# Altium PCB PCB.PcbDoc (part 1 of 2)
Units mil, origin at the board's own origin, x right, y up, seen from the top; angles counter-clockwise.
Board outline 1141.73 x 1220.47 mil, 2 copper layers (Top Layer, Bottom Layer), stack 61.8 mil thick; 114 components, 66 nets, 300 pads, 104 vias.
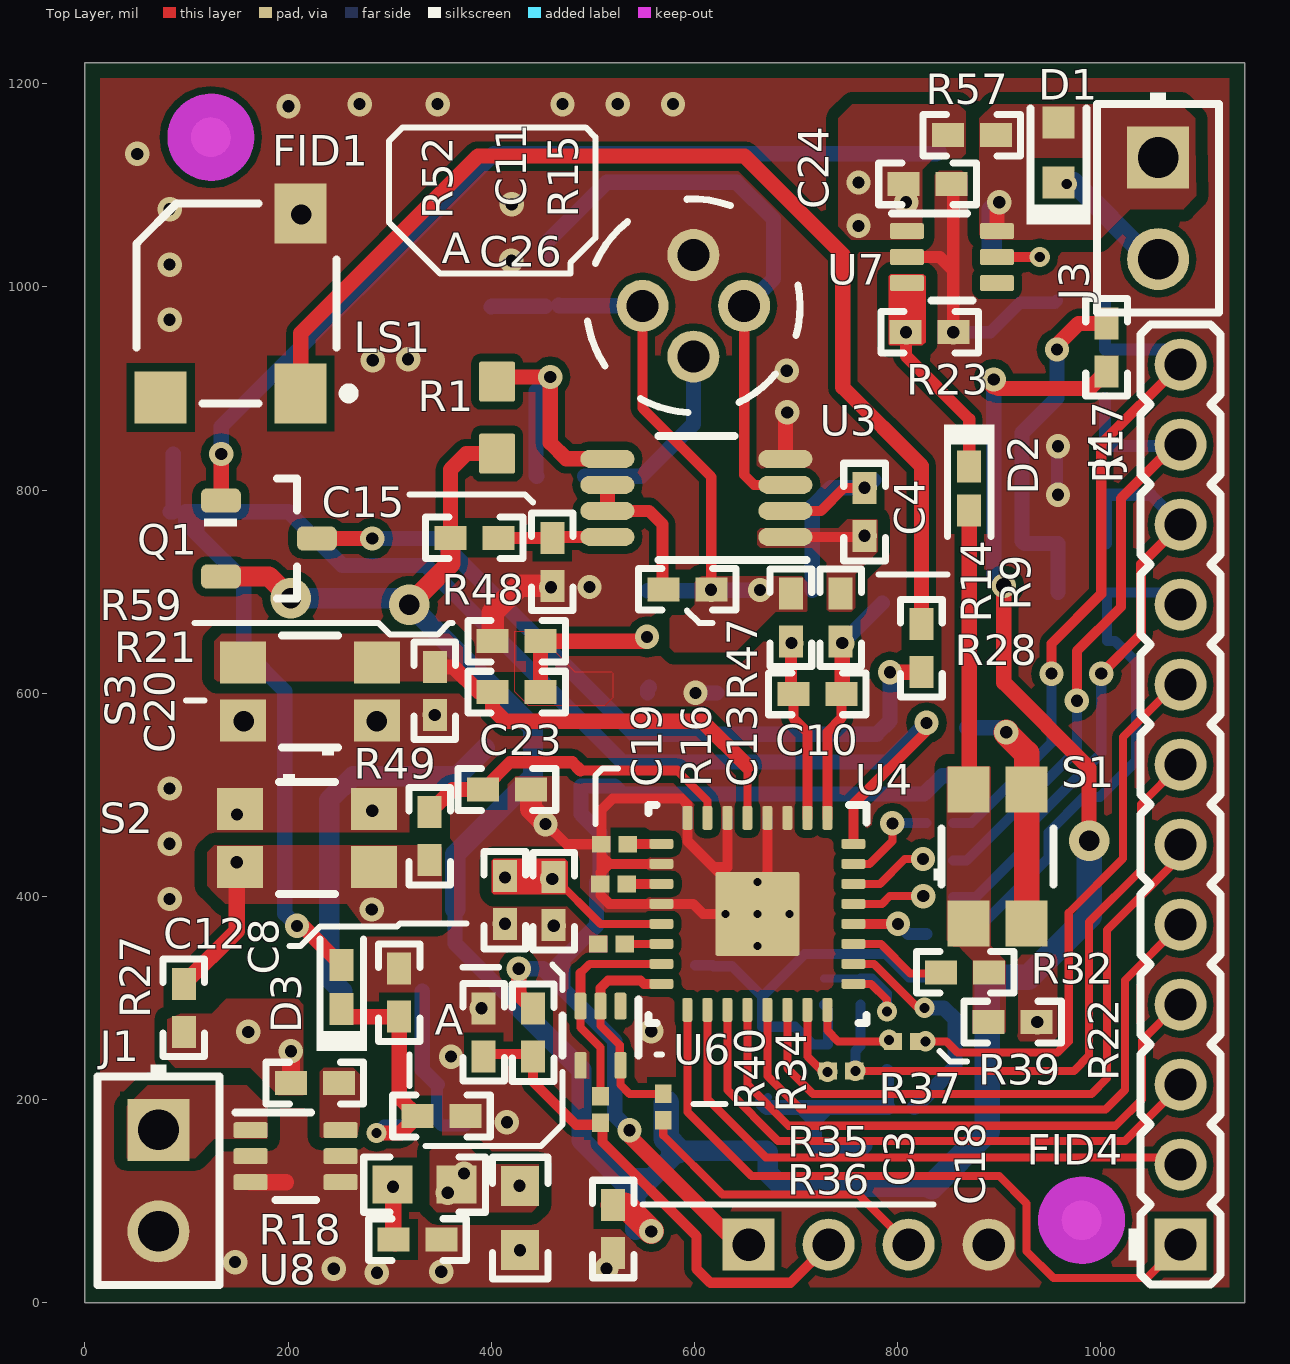
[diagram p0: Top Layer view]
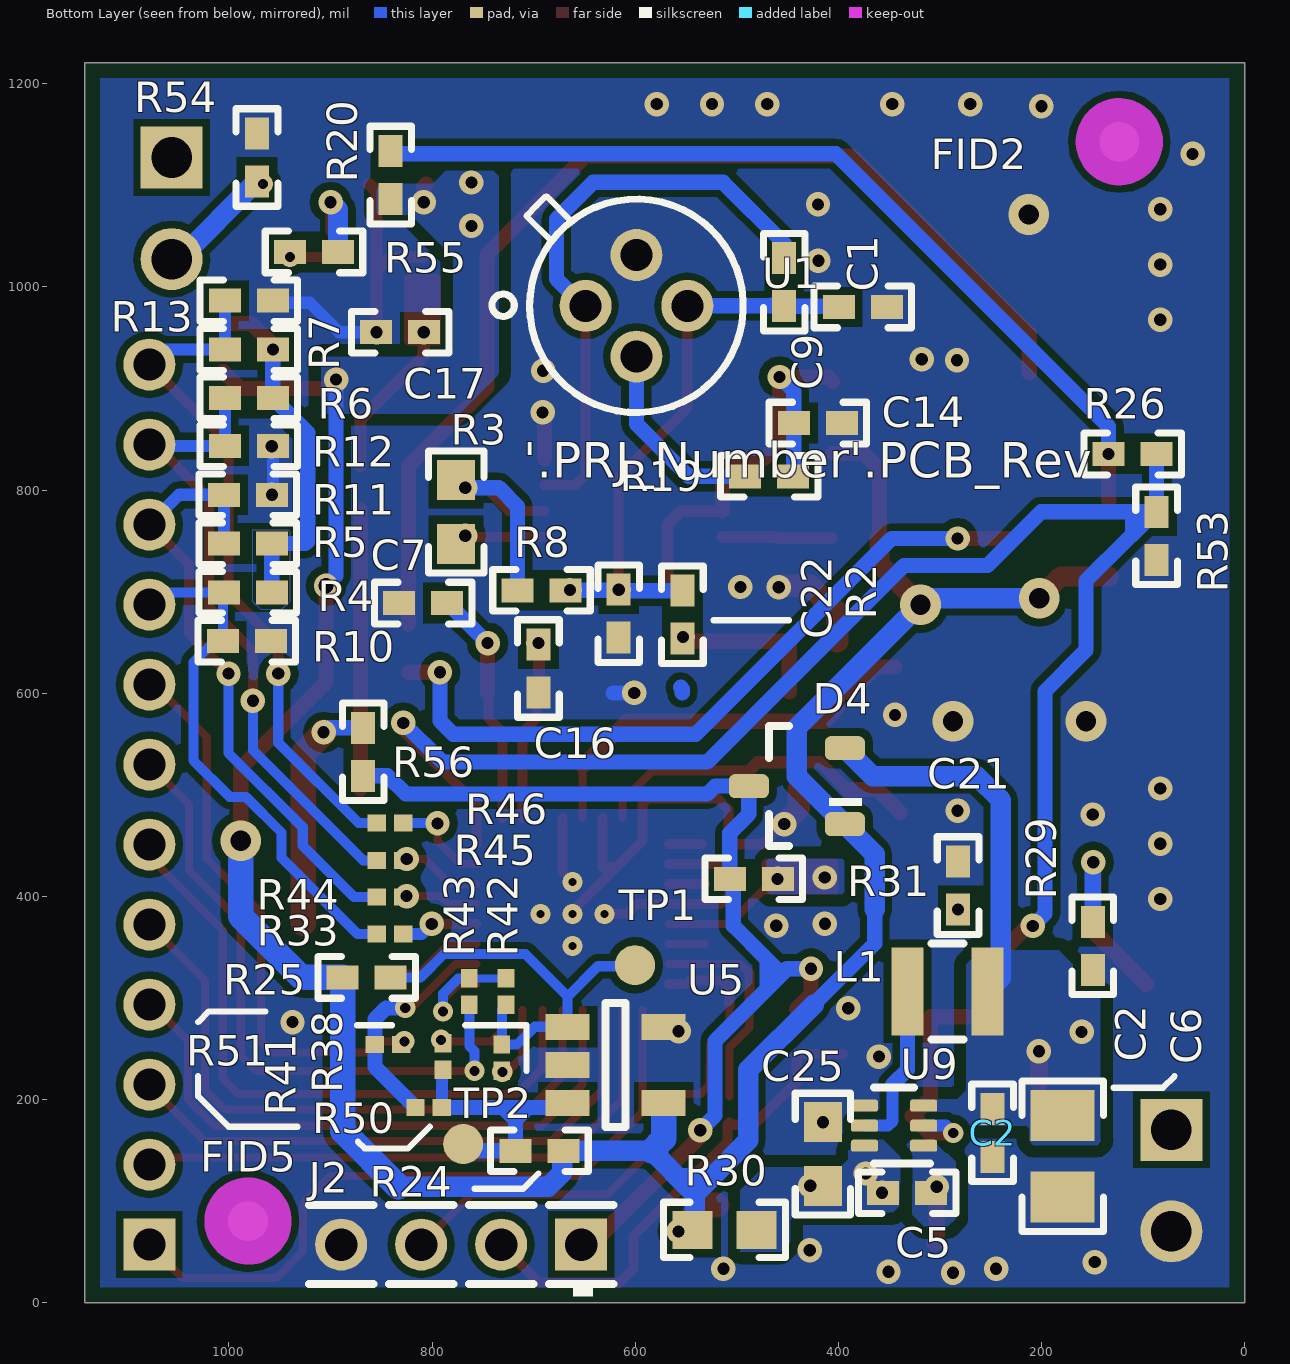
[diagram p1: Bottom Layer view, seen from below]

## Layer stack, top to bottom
Top Solder: solder mask 0.4, Solder Resist, Dk 3.5
Top Layer: signal copper 1.4
Dielectric 2: core 59, FR-4 High TG, Dk 4.2
Bottom Layer: signal copper 1.4
Bottom Solder: solder mask 0.4, Solder Resist, Dk 3.5

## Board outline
0,0 1141.73,0 1141.73,1220.47 0,1220.47

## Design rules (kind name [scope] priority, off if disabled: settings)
AcuteAngle [All] p1: minimum=4.50000000000000E+0001 checktracksonly=FALSE
AssemblyTestPointUsage [All] p1: valid=2
BoardOutlineClearance BoardOutlineClearance_poly [OnCopper and IsPoly] p1: gap=15 ignorepadtopadclearanceinfootprint=FALSE
Clearance [All] p1: gap=7 ignorepadtopadclearanceinfootprint=FALSE except(0: Arc-SMDPad Track-SMDPad; 8: SMDPad-Fill SMDPad-Poly SMDPad-Region Via-Fill Via-Poly Via-Region; 12: Fill-Fill Fill-Poly Fill-Region Poly-Poly Poly-Region Region-Region)
Clearance Clearance_Poly [InPolygon] p2: gap=15 ignorepadtopadclearanceinfootprint=FALSE
ComponentClearance ComponentClearance_TieNet [HasFootprint('Net-Tie_10mil')] p1: gap=0 collisioncheckmode=3 verticalgap=0 showdistances=FALSE
ComponentClearance "ComponentClearance_Spark Gap" [HasFootprint('GAP')] p2: gap=0 collisioncheckmode=3 verticalgap=0 showdistances=FALSE
ComponentClearance ComponentClearance_Logo [InComponentClass(Logo)] p3: gap=0 collisioncheckmode=3 verticalgap=100000 showdistances=FALSE
ComponentClearance ComponentClearance_ScrewToNut [(HasFootprint('NY PMS 440 0025 PH')) vs (HasFootprint('Keystone_1902C'))] p4: gap=10 collisioncheckmode=3 verticalgap=10 showdistances=FALSE
ComponentClearance ComponentClearance_MountingHoles [InComponentClass('Mounting Holes')] p5: gap=25 collisioncheckmode=3 verticalgap=100000 showdistances=FALSE
ComponentClearance ComponentClearance_THtoTH [IsThruComponent vs IsThruComponent] p6: gap=10 collisioncheckmode=3 verticalgap=10 showdistances=FALSE
ComponentClearance [All] p7 off: gap=10 collisioncheckmode=3 verticalgap=10 showdistances=FALSE
DiffPairsRouting [All] p1: maxlimit=100 minlimit=10 mostfreqgap=10 toplayer_minwidth=15 toplayer_maxwidth=15 toplayer_prefwidth=15 bottomlayer_minwidth=15 bottomlayer_maxwidth=15 bottomlayer_prefwidth=15 maxuncoupledlength=1000
FabricationTestPointUsage TestPointUsage [All] p1: valid=2 allowmultiple=FALSE
FabricationTestpoint Testpoint [All] p1: side=3 testpointundercomponent=TRUE minsize=40 maxsize=100 preferedsize=60 minholesize=0 maxholesize=40 preferedholesize=32 testpointgrid=1 allowsidetop=TRUE allowsidebottom=TRUE usegrid=TRUE gridtolerance=0.01
FanoutControl Fanout_LCC [IsLCC] p1: bgadir=Out bgaviamode=Centered fanoutstyle=Auto fanoutdirection=Alternating viagrid=1 // Fanout_LCC (Default Rule)
FanoutControl Fanout_BGA [IsBGA] p2: bgadir=Out bgaviamode=Centered fanoutstyle=Auto fanoutdirection=Alternating viagrid=1 // Fanout_BGA (Default Rule)
FanoutControl Fanout_Default [All] p4: bgadir=Out bgaviamode=Centered fanoutstyle=Auto fanoutdirection=Alternating viagrid=1 // Fanout_Default (Default Rule)
FanoutControl Fanout_Small [(CompPinCount < 5)] p5: bgadir=Out bgaviamode=Centered fanoutstyle=Auto fanoutdirection=OutThenIn viagrid=1 // Fanout_Small (Default Rule)
HoleSize [All] p1: absolutevalues=TRUE maxlimit=251 minlimit=6 maxpercent=80.000 minpercent=20.000
MinimumAnnularRing [All] p1 off: minimumring=5
MinimumSolderMaskSliver "MinimumSolderMaskSliver_Spark Gap" [All vs HasFootprint('SPARK_GAP2')] p1: minsoldermaskwidth=0
MinimumSolderMaskSliver MinimumSolderMaskSliver_Logo [InComponentClass('Logo') vs InComponentClass('Logo')] p2: minsoldermaskwidth=0.7
MinimumSolderMaskSliver [All] p3: minsoldermaskwidth=2
NetAntennae [All] p1 off: netantennaetolerance=10
PlaneConnect [All] p1: planeconnectstyle=Relief reliefexpansion=10 reliefentries=4 reliefconductorwidth=10 reliefairgap=10
PolygonConnect [All] p1: connectstyle=Direct reliefconductorwidth=10 reliefentries=4 polygonreliefangle="90 Angle" airgapwidth=10
RoutingCorners [All] p1: cornerstyle=45-Degree minsetback=5 maxsetback=5
RoutingVias "RoutingVias_Room_.65mm Pitch" [WithinRoom('Room_.65mm Pitch')] p1: holewidth=10 width=20 viastyle="Through Hole" minholewidth=6 minwidth=18 maxholewidth=10 maxwidth=22
RoutingVias [All] p2: holewidth=12 width=24 viastyle="Through Hole" minholewidth=10 minwidth=20 maxholewidth=20 maxwidth=40
SMDNeckDown [All] p1 off: percent=40.000
SMDToCorner [All] p1: distance=0
ShortCircuit [InNet('GND') vs InNet('SIGNAL GND')] p1: allowed=TRUE
SilkToBoardRegionClearance [Not ((IsComment or IsDesignator) And (Hide <> 'False')) and not InRegion(1000,500,4000,800)] p1:
SilkToSilkClearance [All] p1: silktosilkclearance=0
SilkToSolderMaskClearance SilkscreenOverComponentPads_SparkGap [HasFootprint('SPARK_GAP2')] p1 off: minsilkscreentomaskgap=-10 clearancetoexposedcopper=TRUE
SilkToSolderMaskClearance SilkscreenOverComponentPads_1 [All vs All - HasFootprint('SPARK_GAP2')] p2 off: minsilkscreentomaskgap=2 clearancetoexposedcopper=TRUE
SolderMaskExpansion [All] p1: expansion=2
ViasUnderSMD [WithinRoom('Room_.4mm Pitch')] p1: allowed=TRUE
Width [All] p1: maxlimit=100 minlimit=8 preferedwidth=15 checkconnectedcopper=TRUE
12 further rules are at their usual default settings.

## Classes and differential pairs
component class FiducialMark: FID1 FID2 FID4 FID5
component class Header: J1 J2 J3 J4
component class "Host Controller Section_1": C1 C2 C3 C4 C5 C6 C7 C8 C9 C10 C11 C12 C13 C14 C15 C16 C17 C18 C19 C20 C21 C22 C23 C24 C25 C26 D1 D2 D3 D4 J1 J2 J3 J4 L1 LS1 Q1 R1 R2 R3 R4 R5 R6 R7 R8 R9 R10 R11 R12 R13 R14 R15 R16 R17 R18 R19 R20 R21 R22 R23 R24 R25 R26 R27 R28 R29 R30 R31 R32 R33 R34 R35 R36 R37 R38 R39 R40 R41 R42 R43 R44 R45 R46 R47 R48 R49 R50 R51 R52 R53 R54 R55 R56 R57 R59 S1 S2 S3 TP1 TP2 U1 U3 U4 U5 U6 U7 U8 U9
component class Logo: Logo2
component class Hardware: FID1 FID2 FID4 FID5 Logo2 Logo3

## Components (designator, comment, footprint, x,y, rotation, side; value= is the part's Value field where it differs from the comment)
C1 "C1005JB1V105K050BC" 0402 453.43,1004.62 r270 bottom value=1uF
C2 "GRM155R71E104KE14D" 0402 248.37,167.39 r270 bottom value=0.1uF
C3 "GRM188R61A226ME15D" 0603 428.37,83.39 r270 top value=22uF
C4 "C1005JB1V105K050BC" 0402 767.37,778.39 r270 top value=1uF
C5 "GRM1555C1H1R1BA01D" 0402 332.37,108.39 r0 bottom value=1.1pF
C6 "C2012X5R1A336M125AC" 0805_HV 179.37,144.39 r270 bottom value=33uF
C7 "C1005JB1V105K050BC" 0402 808.75,688.77 r0 bottom value=1uF
C8 "GRM155R60J106ME47D" 0402 461.37,395.39 r270 top value=10uF
C9 "C1005JB1V105K050BC" 0402 376.15,980.31 r180 bottom value=1uF
C10 "C1005JB1V105K050BC" 0402 720.87,599.39 r180 top value=1uF
C11 "C0402C112J5GAC7867" 0402 392.47,266.39 r90 top value=1100pF
C12 "GRM155R71E104KE14D" 0402 413.37,396.39 r270 top value=0.1uF
C13 "GRM033R60J474KE90D" 0201_033 518.37,353.39 r180 top value=0.47uF
C14 "C1005JB1V105K050BC" 0402 420.42,866 r180 bottom value=1uF
C15 "C1005JB1V105K050BC" 0402 460.06,729.39 r270 top value=1uF
C16 "C1005JB1V105K050BC" 0402 695.37,624.39 r270 bottom value=1uF
C17 "C1005JB1V105K050BC" 0402 831.37,955.39 r0 bottom value=1uF
C18 "C1005JB1V105K050BC" 0402 519.97,72.77 r270 top value=1uF
C19 "GRM033R61E104KE14J" 0201_033 521.37,451.39 r180 top value=0.1uF
C20 "GRM155R71E104KE14D" 0402 344.37,602.39 r270 top value=0.1uF
C21 "GRM155R71E104KE14D" 0402 282.37,410.8 r90 bottom value=0.1uF
C22 "GRM155R71E104KE14D" 0402 616.37,678.39 r270 bottom value=0.1uF
C23 "GRM155R71E104KE14D" 0402 415.37,505.34 r0 top value=0.1uF
C24 "C1005JB1V105K050BC" 0402 829.37,1101.39 r180 top value=1uF
C25 "GRM188R61A226ME15D" 0603 415.37,146.39 r90 bottom value=22uF
C26 "GRM155R71E104KE14D" 0402 350.99,183.96 r0 top value=0.1uF
D1 "LTST-C190GKT" LED_LTST-C190 958.37,1132.39 r270 top value=Green
D2 "1N4148X-TP" SOD-523 870.37,801.74 r270 top value=75V
D3 "1N4148X-TP" SOD-523 252.75,310.71 r90 top value=75V
D4 "BAT54C-7-F" SOT-23 441.05,508.67 r0 bottom value=30V
FID1 "Fiducial" Fiducial10-20 123.85,1147.32 r0 top
FID2 "Fiducial" Fiducial10-20 123.65,1142.86 r180 bottom
FID4 "Fiducial" Fiducial10-20 980.98,81.35 r0 top
FID5 "Fiducial" Fiducial10-20 981.24,80.53 r180 bottom
J1 "PEC01DAAN" Sullins_PxC01DAAN 72.37,120.39 r270 top
J2 "PTT-104-01-L-S" Samtec_PTT-104-01-x-S 771.37,57.39 r0 bottom
J3 "PEC01DAAN" Sullins_PxC01DAAN 1056.37,1077.39 r270 top
J4 "M22-2511205" Harwin_M22-2511205 1078.37,490.46 r90 top
L1 "LQM2HPN2R2MG0L" 1008 292.75,306.74 r180 bottom value=2.2uH
Logo2 "Texas Instruments" TI_Stacked_Overlay_Small 1290.23,404.73 r90 top
Logo3 "FCC disclaimer" FCC_disclaimer 3078.31,4369.38 r0 top
LS1 "SMT-0540-T-2-R" PUI_SMT-0540-S-R 149.37,983.8 r180 top
Q1 "BC857C-7-F" SOT-23 181.07,752.39 r0 top value="45 V"
R1 "CPF0603B1M0E1" CPF_0603 405.7,871.37 r270 top value=1.00Meg
R2 "CRCW04020000Z0ED" 0402 553.62,677.39 r270 bottom value=0
R3 "RG1608P-204-B-T5" 0603 776.37,778.39 r270 bottom value=200k
R4 "RC0402FR-0747KL" 0402 981.37,699.39 r180 bottom value=47.0k
R5 "RC0402FR-0747KL" 0402 981.37,747.39 r180 bottom value=47.0k
R6 "RC0402FR-0747KL" 0402 980.37,890.74 r180 bottom value=47.0k
R7 "RC0402FR-0747KL" 0402 980.37,938.39 r180 bottom value=47.0k
R8 "ERA-2AEB102X" 0402 692.37,701.39 r0 bottom value=1.00k
R9 "CRCW04021K00JNED" 0402 743.87,674.39 r270 top value=1.0k
R10 "RC0402FR-0747KL" 0402 982.37,651.39 r0 bottom value=47.0k
R11 "RC0402FR-0747KL" 0402 981.37,795.39 r0 bottom value=47.0k
R12 "RC0402FR-0747KL" 0402 980.37,843.57 r0 bottom value=47.0k
R13 "RC0402FR-0747KL" 0402 980.37,986.39 r0 bottom value=47.0k
R14 "CRCW04021K00JNED" 0402 694.87,674.39 r270 top value=1.0k
R15 "RC0402FR-0747KL" 0402 441.05,265.99 r90 top value=47.0k
R16 "ERJ-1GE0R00C" 0201 520.37,412.39 r0 top value=0
R17 "CRCW04020000Z0ED" 0402 1005.54,940.46 r270 top value=0
R18 "CRCW04020000Z0ED" 0402 226.37,216.39 r180 top value=0
R19 "RT0402BRD07102KL" 0402 468.24,813.64 r180 bottom value=102k
R20 "CRCW0402100KJNED" 0402 840.75,1110.11 r270 bottom value=100k
R21 "CRCW04021K00JNED" 0402 424.87,601.27 r180 top value=1.0k
R22 "ERJ-2RKF4701X" 0402 913.1,276.39 r180 top value=4.70k
R23 "CRCW040210M0JNED" 0402 831.37,955.39 r180 top value=10Meg
R24 "CRCW04022K20JNED" 0402 694.37,149.71 r180 bottom value=2.2k
R25 "CRCW04022K20JNED" 0402 864.37,320.39 r0 bottom value=2.2k
R26 "CRCW0402100KJNED" 0402 110.54,835.53 r0 bottom value=100k
R27 "RC0402FR-0747KL" 0402 97.37,290.39 r270 top value=47.0k
R28 "CRCW0402680RJNED" 0402 823.37,644.39 r270 top value=680
R29 "CRCW040217K4FKED" 0402 149.75,351.41 r90 bottom value=17.4k
R30 "ERJ-3GEY0R00V" 0603 512.1,71.83 r180 bottom value=0
R31 "ERJ-2RKF33R0X" 0402 483.37,417.39 r180 bottom value=33.0
R32 "CRCW04020000Z0ED" 0402 866.37,325.39 r180 top value=0
R33 "ERJ-1GE0R00C" 0201 841.37,363.02 r0 bottom value=0
R34 "ERJ-1GE0R00C" 0201 569.25,192.73 r90 top value=0
R35 "RT0603BRD07453KL" 0603 334.37,116.39 r0 top value=453k
R36 "RG1005P-104-B-T5" 0402 327.37,62.39 r180 top value=100k
R37 "ERJ-1GE0R00C" 0201 744.36,228.39 r0 top value=0
R38 "ERJ-1GE0R00C" 0201 731.37,241.39 r90 bottom value=0
R39 "ERJ-1GE0R00C" 0201 808.32,257.39 r0 top value=0
R40 "ERJ-1GE0R00C" 0201 507.37,190.39 r90 top value=0
R41 "ERJ-1GE0R00C" 0201 789.35,242.39 r270 bottom value=0
R42 "ERJ-1GE0R00C" 0201 727.37,306.39 r270 bottom value=0
R43 "ERJ-1GE0R00C" 0201 763.37,306.39 r270 bottom value=0
R44 "ERJ-1GE0R00C" 0201 841.37,399.39 r0 bottom value=0
R45 "ERJ-1GE0R00C" 0201 841.37,435.39 r0 bottom value=0
R46 "ERJ-1GE0R00C" 0201 841.37,472.39 r0 bottom value=0
R47 "ERJ-2GEJ101X" 0402 592.87,702.39 r0 top value=100
R48 "ERJ-2RKF33R0X" 0402 383.37,753.01 r0 top value=33.0
R49 "CRCW04021K00JNED" 0402 339.37,459.39 r90 top value=1.0k
R50 "ERJ-1GE0R00C" 0201 803.36,192.39 r180 bottom value=0
R51 "ERJ-1GE0R00C" 0201 843.33,254.39 r180 bottom value=0
R52 "CRCW0402100KJNED" 0402 309.37,305.34 r270 top value=100k
R53 "CRCW040222K0JNED" 0402 86.91,755.01 r90 bottom value=22k
R54 "CRCW0402680RJNED" 0402 972.37,1127.39 r270 bottom value=680
R55 "CRCW0402100RJNED" 0402 916.25,1034.39 r180 bottom value=100
R56 "CRCW0402100RJNED" 0402 867.79,542.39 r270 bottom value=100
R57 "CRCW04020000Z0ED" 0402 872.99,1149.33 r180 top value=0
R59 "RC0402FR-0747KL" 0402 424.87,651.27 r0 top value=47.0k
S1 "434153017835" SW_434153017835 898.37,439.39 r90 top
S2 "434153017835" SW_434153017835 218.37,457.39 r0 top
S3 "434153017835" SW_434153017835 221.31,601.85 r180 top
TP1 "TP_SM_1MM" TP_SM_1MM 600.37,332.39 r90 bottom
TP2 "TP_SM_1MM" TP_SM_1MM 769.37,156.39 r90 bottom
U1 "TS318-11C55" TE_TS318-11C55 598.87,981.39 r90 bottom locked
U3 "TLV2333IDGKR" DGK0008A_N 601.87,792.39 r180 top
U4 "MSP430I2041TRHBR" RHB0032M 661.84,382.9 r270 top locked
U5 "AT24C02C-STUM-T" SOT-23-5 619.37,234.39 r180 bottom
U6 "TPD2E2U06DRLR" DRL0005A 507.37,263.02 r270 top
U7 "TPS22919DCKR" DCK0006A_N 853.37,1029.39 r0 top
U8 "LM66100DCKR" DCK0006A_N 207.37,144.39 r0 top
U9 "TPS61023DRL" DRL0006A 345.37,174.39 r0 bottom

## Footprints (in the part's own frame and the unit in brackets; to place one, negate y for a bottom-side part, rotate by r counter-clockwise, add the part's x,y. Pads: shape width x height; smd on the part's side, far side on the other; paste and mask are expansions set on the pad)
0201 [mm] "Data from Kemet datasheet CC101_COM dated 7/28/11"
  rect 0.46x0.42 smd mask+0.048: 1(-0.33,0) 2(0.33,0)
  body extent -0.31,-0.16 0.31,0.16, height 0.26
0201_033 [mm] "SMD, 2-Leads, Height 0.33mm"
  rect 0.46x0.42 smd mask+0.048: 1(-0.33,0) 2(0.33,0)
  body extent -0.31,-0.16 0.31,0.16, height 0.33
0402 [mm] "0402 from SM-752 data"
  rect 0.8x0.6 smd: 1(-0.6,0) 2(0.6,0)
  silkscreen extent -1.22,-0.52 1.22,0.52, body extent -0.55,-0.3 0.55,0.3, height 0.6
0603 [mm] "0603 from SM-752 data"
  rect 1x0.95 smd: 1(-0.8,0) 2(0.8,0)
  silkscreen extent -1.52,-0.69 1.52,0.69, body extent -0.87,-0.47 0.87,0.47, height 1
0805_HV [mil] "0805 with 30mil clearance between pads"
  rect 50x63 smd: 1(-40,0) 2(40,0)
  silkscreen extent -74,-40 74,40, body extent -43,-29 43,29, height 57
1008 [mm] "SMD, Body 2.5x2mm, Height 1.2mm"
  rect 0.8x2.2 smd: 1(-1,0) 2(1,0)
  silkscreen extent -0.4,-1.2 0.4,1.2, body extent -1.35,-1.1 1.35,1.1, height 1.2
CPF_0603 [mm] "SMD, 2-Leads, Body 1.55x0.8mm"
  rrect11% 1x0.9 smd: 1(-0.9,0) 2(0.9,0)
  body extent -0.82,-0.45 0.82,0.45, height 0.55
DCK0006A_N [mm] "SOT23, 6-Leads, Body 2x1.3mm, Pitch 0.65mm, Lead Span 2.1mm, IPC Medium Density"
  rrect25% 0.85x0.4 smd: 1(-1.125,0.65) 2(-1.125,0) 3(-1.125,-0.65) 4(1.125,-0.65) 5(1.125,0) 6(1.125,0.65)
  silkscreen extent -1.5,-1.09 0.51,1.09, body extent -1.14,-1 1.14,1, height 0.95
DGK0008A_N [mm] "TSOP, 8-Leads, Body 3x3mm, Pitch 0.65mm, IPC Medium Density"
  oval 1.35x0.45 smd: 1(-2.225,0.975) 2(-2.225,0.325) 3(-2.225,-0.325) 4(-2.225,-0.975) 5(2.225,-0.975) 6(2.225,-0.325) 7(2.225,0.325) 8(2.225,0.975)
  silkscreen extent -2.75,-1.55 0.95,1.55, body extent -2.45,-1.5 2.45,1.5, height 0.96
DRL0005A [mm] "SOTFL, 5-Flat Leads, Body 1.2x1.6x0.6mm, Pitch 0.5mm, TI recommended"
  rrect33% 0.67x0.3 smd: 1(-0.74,0.5) 2(-0.74,0) 3(-0.74,-0.5) 4(0.74,-0.5) 5(0.74,0.5)
  silkscreen extent -0.9,-0.95 0.5,0.95, body extent -0.85,-0.85 0.85,0.85, height 0.62
DRL0006A [mm] "SOTFL, 6-Flat Leads, Body 1.2x1.6x0.6mm, Pitch 0.5mm, TI recommended"
  rrect33% 0.67x0.3 smd: 1(-0.74,0.5) 2(-0.74,0) 3(-0.74,-0.5) 4(0.74,-0.5) 5(0.74,0) 6(0.74,0.5)
  silkscreen extent -0.9,-0.95 0.5,0.95, body extent -0.8,-0.8 0.8,0.8, height 0.61
FCC_disclaimer [mil]
Fiducial10-20 [mm]
  round 1 smd mask+0.5: 1(0,0)
  Top Layer keep-out circle w1.178: c0,0 r0.5
Harwin_M22-2511205 [mm] "Header, 2mm, 12x1, TH"
  rect 1.3x1.3 hole 0.8: 1(-11,0)
  round 1.3 hole 0.8: 2(-9,0) 3(-7,0) 4(-5,0) 5(-3,0) 6(-1,0) 7(1,0) 8(3,0) 9(5,0) 10(7,0) 11(9,0) 12(11,0)
  silkscreen extent -12,-1 12,1.3, body extent -12,-1 12,1, height 5
LED_LTST-C190 [mm] "Lite-On"
  rect 0.8x0.8 smd: 1(-0.75,0) 2(0.75,0)
  silkscreen extent -1.1,-0.8 1.8,0.8, body extent -0.85,-0.45 0.85,0.45, height 0.9
PUI_SMT-0540-S-R [mm] "SMD, 3-Leads, Body 5x5mm"
  rect 1.3x1.5 smd: 1(-1.6,2.25) 2(-1.6,-2.25)
  rect 1.3x1.3 smd: 3(1.9,2.35)
  silkscreen extent -2.93,-2.5 2.5,2.5, body extent -2.5,-2.7 2.5,2.7, height 2
RHB0032M [mm] "QFN, 32-Leads, Body 5x5mm, Pitch 0.5mm, Thermal Pad 2.1x2.1mm"
  rrect40% 0.6x0.25 smd: 1(-2.4,1.75) 2(-2.4,1.25) 3(-2.4,0.75) 4(-2.4,0.25) 5(-2.4,-0.25) 6(-2.4,-0.75) 7(-2.4,-1.25) 8(-2.4,-1.75) 17(2.4,-1.75) 18(2.4,-1.25) 19(2.4,-0.75) 20(2.4,-0.25) 21(2.4,0.25) 22(2.4,0.75) 23(2.4,1.25) 24(2.4,1.75)
  rrect40% 0.25x0.6 smd: 9(-1.75,-2.4) 10(-1.25,-2.4) 11(-0.75,-2.4) 12(-0.25,-2.4) 13(0.25,-2.4) 14(0.75,-2.4) 15(1.25,-2.4) 16(1.75,-2.4) 25(1.75,2.4) 26(1.25,2.4) 27(0.75,2.4) 28(0.25,2.4) 29(-0.25,2.4) 30(-0.75,2.4) 31(-1.25,2.4) 32(-1.75,2.4)
  rrect11% 0.94x0.94 on Top Paste: 33(-0.57,0.57) 33(-0.57,-0.57) 33(0.57,-0.57) 33(0.57,0.57)
  rrect5% 2.1x2.1 smd paste-1.725: 33(0,0)
  silkscreen extent -2.73,-2.73 2.73,2.72, body extent -2.55,-2.55 2.55,2.55, height 1.01
Samtec_PTT-104-01-x-S [mm] "Header, 2mm, 4x1, TH"
  rect 1.3x1.3 hole 0.81: 1(-3,0)
  round 1.3 hole 0.81: 2(-1,0) 3(1,0) 4(3,0)
  silkscreen extent -3.81,-0.99 3.81,1.3, body extent -4,-0.99 4,0.99, height 4.7
SOD-523 [mm] "NXP Semiconductor recommended land pattern, nominal STEP model"
  rect 0.8x0.6 smd paste-0.05: 1(-0.55,0) 2(0.55,0)
  silkscreen extent -1.6,-0.64 1.2,0.63, body extent -0.8,-0.4 0.8,0.4, height 0.72
SOT-23 [mm] "SOT23, 3-Leads, Body 2.9x1.3mm, Pitch 0.95mm, Lead Span 2.5mm, IPC Medium Density"
  rrect50% 1x0.6 smd: 1(-1.2,0.95) 2(-1.2,-0.95) 3(1.2,0)
  silkscreen extent -1.62,-1.5 0.7,1.5, body extent -1.16,-1.45 1.21,1.45, height 1
SOT-23-5 [mm] "SOT23, 5-Leads, Body 2.9x1.6mm, Pitch 0.95mm, Lead Span 2.8mm, IPC Medium Density"
  rect 1.1x0.65 smd: 1(-1.2,0.95) 2(-1.2,0) 3(-1.2,-0.95) 4(1.2,-0.95) 5(1.2,0.95)
  silkscreen extent -0.25,-1.55 0.25,1.55, body extent -1.42,-1.46 1.42,1.46, height 1.08
Sullins_PxC01DAAN [mm] "Header, 2.54mm, 1x2, TH"
  rect 1.55x1.55 hole 1.016: 1(-1.27,0)
  round 1.55 hole 1.016: 2(1.27,0)
  silkscreen extent -2.9,-1.53 2.61,1.53, body extent -2.61,-1.53 2.61,1.53, height 8.71
SW_434153017835 [mm] "SMD, 4-Leads, Body 3.5x2.9mm"
  rect 1.15x1.05 smd: 1(-1.675,0.725) 2(-1.675,-0.725) 3(1.675,0.725) 4(1.675,-0.725)
  silkscreen extent -0.7,-1.4 0.7,1.6, body extent -2.15,-1.45 2.15,1.45, height 1.7
TE_TS318-11C55 [mm] "THERMOPHILE SENSOR, TO-18, TH-4P"
  round 1.3 hole 0.8: 1(0,1.27) 2(-1.27,0) 3(0,-1.27) 4(1.27,0)
  silkscreen extent -2.67,-2.67 2.73,3.61, body extent -2.67,-2.67 2.67,2.67, height 2.85
TI_Stacked_Overlay_Small [mil]
  silkscreen extent -418,-98 418,98
TP_SM_1MM [mm] "1mm Test Point, SMT"
  round 1 smd paste-0.5: 1(0,0)

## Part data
C1 C4 C7 C9 C10 C14 C15 C16 C17 C18 C24: library part CMP-0006253-2, "CAP, CERM, 1 uF, 35 V, +/- 10%, JB, 0402", Cap_Case=0402, Manufacturer=TDK, Supplier Part Number 1=445-11014-1-ND, TempCo=JB, Tolerance_%=10%, Value1=Unknown, Value2=35V, ValueDisplayed=1uF
C2 C12 C20 C21 C22 C23 C26: "CAP, CERM, 0.1 µF, 25 V,+/- 10%, X7R, 0402", Cap_Case=0402, Manufacturer=MuRata, Supplier Part Number 1=490-10698-1-ND, TempCo=X7R, Tolerance_%=10, Value2=25V, ValueDisplayed=0.1µF
C3 C25: "CAP, CERM, 22 µF, 10 V,+/- 20%, X5R, 0603", Cap_Case=0603, Manufacturer=MuRata, Supplier Part Number 1=490-10476-1-ND, TempCo=X5R, Tolerance_%=20, Value2=10V, ValueDisplayed=22µF
C5: "CAP, CERM, 1.1 pF, 50 V,+/- 10%, C0G/NP0, 0402", Cap_Case=0402, Manufacturer=MuRata, Supplier Part Number 1=490-8189-1-ND, TempCo=C0G/NP0, Tolerance_%=10, Value2=50V, ValueDisplayed=1.1pF
C6: "CAP, CERM, 33 µF, 10 V,+/- 20%, X5R, 0805", Cap_Case=0805, Manufacturer=TDK, Supplier Part Number 1=445-8238-1-ND, TempCo=X5R, Tolerance_%=20, Value1="0.001694 ohm", Value2=10V, ValueDisplayed=33µF
C8: library part CMP-0078624-1, "CAP, CERM, 10 µF, 6.3 V,+/- 20%, X5R, 0402", Cap_Case=0402, Manufacturer=MuRata, Supplier Part Number 1=490-13239-1-ND, TempCo=X5R, Tolerance_%=20%, Value2=6.3V, ValueDisplayed=10µF
C11: library part CMP-0006238-2, "CAP, CERM, 1100 pF, 50 V, +/- 5%, C0G/NP0, 0402", Cap_Case=0402, Manufacturer=Kemet, Supplier Part Number 1=399-9948-1-ND, TempCo=C0G/NP0, Tolerance_%=5%, Value1=Unknown, Value2=50V, ValueDisplayed=1100pF
C13: "CAP, CERM, 0.47 µF, 6.3 V,+/- 10%, X5R, 0201", Cap_Case=0201, Manufacturer=MuRata, Supplier Part Number 1=490-10409-1-ND, TempCo=X5R, Tolerance_%=10, Value2=6.3V, ValueDisplayed=0.47µF
C19: "CAP, CERM, 0.1 µF, 25 V,+/- 10%, X5R, 0201", Cap_Case=0201, Manufacturer=MuRata, Supplier Part Number 1=GRM033R61E104KE14D-ND, TempCo=X5R, Tolerance_%=10, Value2=25V, ValueDisplayed=0.1µF
D1: library part CMP-0002827-2, "LED, Green, SMD", Color=green, Manufacturer=Lite-On, Power_TotalModule=100mW, Supplier Part Number 1=160-1183-1-ND, Value1=0.1W, Value2=2.1V
D2 D3: library part CMP-0076957-1, "Diode, Switching, 75 V, 0.3 A, SOD-523", Manufacturer="Micro Commercial Components", Supplier Part Number 1=1N4148XTPMSCT-ND, Value1=0.3A, Value2=1.25V
D4: library part CMP-0028453-2, "Diode, Schottky, 30 V, 0.2 A, SOT-23", Manufacturer="Diodes Inc.", Value1=0.2A, Value2=0.65V
FID1 FID2 FID4 FID5: library part CMP-0077181-1, "Fiducial mark.  There is nothing to buy or mount.", Manufacturer=N/A
J1 J3: library part CMP-0054594-1, "Header, 2.54mm, 1x2, Tin, Black, TH", Color=Black, Current_A=3A, Manufacturer="Sullins Connector Solutions", Supplier Part Number 1=S2012E-01-ND, Voltage_V=1.8kV
J2: library part CMP-0055572-1, "Header, 2mm, 4x1, Gold, TH", Color=Black, Current_A=2.9A, Manufacturer=Samtec
J4: library part CMP-0075238-1, "Header, 2mm, 12x1, Gold, TH", Color=Black, Current_A=1A, Manufacturer=Harwin, Supplier Part Number 1=M22-2511205-ND, Voltage_V=500V
L1: library part CMP-0058752-1, "Inductor, Multilayer, Ferrite, 2.2 uH, 1.3 A, 0.08 ohm, SMD", Manufacturer=MuRata, Supplier Part Number 1=490-5114-1-ND, Value1="0.08 ohm", Value2=1.3A, ValueDisplayed=2.2uH
Logo2: library part CMP-0074838-1, "Texas Instrument Corporate Signature"
Logo3: library part CMP-0074847-1, "FCC_disclaimer"
LS1: library part CMP-0001959-1, "Buzzer, 2 to 4V, 4kHz, SMD", Manufacturer="PUI Audio", Supplier Part Number 1=668-1060-1-ND
Q1: library part CMP-0000316-2, "Transistor, PNP, 45 V, 0.1 A, SOT-23", Manufacturer="Diodes Inc.", Supplier Part Number 1=BC857C-FDICT-ND, Value1="0.1 A", Value2=600
R1: library part CMP-0079989-2, "RES, 1.00 M, 0.1%, 0.063 W, 0603", Manufacturer="TE Connectivity", Power_W=63mW, Supplier Part Number 1=A102234CT-ND, TempCo="25 ppm/C", Tolerance_%=0.1%, Value2=0.063W, Value_Code=1M00, ValueDisplayed=1.00M
R2 R17 R18 R32 R57: library part CMP-0026822-1, "RES, 0, 5%, 0.063 W, 0402", Manufacturer=Vishay-Dale, Power_W=63mW, Supplier Part Number 1=541-0.0JCT-ND, TempCo="200 ppm/C", Tolerance_%=5%, Value2=0.063W, Value_Code=0000, ValueDisplayed=0
R3: "RES, 200 k, 0.1%, 0.1 W, 0603", Manufacturer="Susumu Co Ltd", Power_W=0.1, Supplier Part Number 1=RG16P200KBCT-ND, TempCo="25 ppm/C", Tolerance_%=0.1%, Value2=0.1W, Value_Code=200k
R4 R5 R6 R7 R10 R11 R12 R13 R15 R27 R59: "RES, 47.0 k, 1%, 0.0625 W, 0402", Manufacturer="Yageo America", Power_W=0.0625, Supplier Part Number 1=311-47.0KLRCT-ND, TempCo="100 ppm/C", Tolerance_%=1, Value1=1%, Value2=0.0625W, Value_Code=47k0, ValueDisplayed=47.0k
R8: "RES, 1.00 k, 0.1%, 0.063 W, 0402", Manufacturer=Panasonic, Power_W=0.063, Supplier Part Number 1=P1.0KDCCT-ND, TempCo="25 ppm/C", Tolerance_%=0.1%, Value2=0.063W, Value_Code=1k00, ValueDisplayed=1.00k
R9 R14 R21 R49: library part CMP-0026852-3, "RES, 1.0 k, 5%, 0.063 W, AEC-Q200 Grade 0, 0402", Manufacturer=Vishay-Dale, Power_W=63mW, Supplier Part Number 1=541-1.0KJCT-ND, TempCo="200 ppm/C", Tolerance_%=5%, Value2=0.063W, Value_Code=1k00, ValueDisplayed=1.0k
R16 R33 R34 R37 R38 R39 R40 R41 R42 R43 R44 R45 R46 R50 R51: "RES, 0, 5%, 0.05 W, 0201", Manufacturer=Panasonic, Power_W=0.05, Supplier Part Number 1=P0.0AGCT-ND, TempCo="600 ppm/C", Tolerance_%=5, Value1=5%, Value2=0.05W, Value_Code=0000, ValueDisplayed=0
R19: library part RG1005P-104-B-T5, "RES, 100 k, 0.1%, 0.063 W, 0402", Manufacturer=Yageo, Power_W=0.063, TempCo="25 ppm/C", Tolerance_%=0.1%, Value2=0.063W, Value_Code=102k
R20 R26 R52: "RES, 100 k, 5%, 0.063 W, 0402", Manufacturer=Vishay-Dale, Power_W=0.063, Supplier Part Number 1=541-100KJCT-ND, TempCo="200 ppm/C", Tolerance_%=5, Value1=5%, Value2=0.063W, Value_Code=100k
R22: "RES, 4.70 k, 1%, 0.1 W, 0402", Manufacturer=Panasonic, Power_W=0.1, Supplier Part Number 1=P4.70KLCT-ND, TempCo="100 ppm/C", Tolerance_%=1, Value1=1%, Value2=0.1W, Value_Code=4k70, ValueDisplayed=4.70k
R23: "RES, 10 M, 5%, 0.063 W, 0402", Manufacturer=Vishay-Dale, Power_W=0.063, Supplier Part Number 1=541-10MJCT-ND, TempCo="200 ppm/C", Tolerance_%=5, Value1=5%, Value2=0.063W, Value_Code=10M0, ValueDisplayed=10M
R24 R25: library part CMP-0026890-3, "RES, 2.2 k, 5%, 0.063 W, 0402", Manufacturer=Vishay-Dale, Power_W=63mW, Supplier Part Number 1=541-2.2KJCT-ND, TempCo="200 ppm/C", Tolerance_%=5%, Value2=0.063W, Value_Code=2k20, ValueDisplayed=2.2k
R28 R54: "RES, 680, 5%, 0.063 W, 0402", Manufacturer=Vishay-Dale, Power_W=0.063, Supplier Part Number 1=541-680JCT-ND, TempCo="200 ppm/C", Tolerance_%=5, Value1=5%, Value2=0.063W, Value_Code=680R, ValueDisplayed=680
R29: "RES, 17.4 k, 1%, 0.063 W, 0402", Manufacturer=Vishay-Dale, Power_W=0.063, Supplier Part Number 1=541-17.4KLCT-ND, TempCo="100 ppm/C", Tolerance_%=1, Value1=1%, Value2=0.063W, Value_Code=17k4, ValueDisplayed=17.4k
R30: "RES, 0, 5%, 0.1 W, 0603", Manufacturer=Panasonic, Power_W=0.1, Supplier Part Number 1=P0.0GCT-ND, TempCo="600 ppm/C", Tolerance_%=5, Value1=5%, Value2=0.1W, Value_Code=0000, ValueDisplayed=0
R31 R48: "RES, 33.0, 1%, 0.1 W, 0402", Manufacturer=Panasonic, Power_W=0.1, Supplier Part Number 1=P33.0LCT-ND, TempCo="100 ppm/C", Tolerance_%=1, Value1=1%, Value2=0.1W, Value_Code=33R0, ValueDisplayed=33.0
R35: "RES, 453 k, 0.1%, 0.1 W, 0603", Manufacturer="Yageo America", Power_W=0.1, TempCo="25 ppm/C", Value1=0.1%, Value2=0.1W, Value_Code=453k
R36: "RES, 100 k, 0.1%, 0.063 W, 0402", Manufacturer="Susumu Co Ltd", Power_W=0.063, Supplier Part Number 1=RG10P100KBCT-ND, TempCo="25 ppm/C", Tolerance_%=0.1%, Value2=0.063W, Value_Code=100k
R47: "RES, 100, 5%, 0.1 W, AEC-Q200 Grade 0, 0402", Manufacturer=Panasonic, Power_W=0.1, Supplier Part Number 1=P100JCT-ND, TempCo="200 ppm/C", Tolerance_%=5, Value1=5%, Value2=0.1W, Value_Code=100R, ValueDisplayed=100
R53: "RES, 22 k, 5%, 0.063 W, 0402", Manufacturer=Vishay-Dale, Power_W=0.063, Supplier Part Number 1=541-22KJCT-ND, TempCo="200 ppm/C", Tolerance_%=5, Value1=5%, Value2=0.063W, Value_Code=22k0, ValueDisplayed=22k
R55 R56: "RES, 100, 5%, 0.063 W, 0402", Manufacturer=Vishay-Dale, Power_W=0.063, Supplier Part Number 1=541-100JCT-ND, TempCo="200 ppm/C", Tolerance_%=5, Value1=5%, Value2=0.063W, Value_Code=100R, ValueDisplayed=100
S1 S2 S3: library part CMP-0002302-1, "Switch, SPST, Off-Mom, 0.05 A, 12 VDC, SMD", CurrentRating_mA=50A, Manufacturer="Wurth Elektronik", Supplier Part Number 1=732-10143-1-ND
TP1 TP2: library part CMP-0003825-1, "1mm Test Point, SMT", Manufacturer=Any
U1: "THERMOPILE IR SENSOR, HIGH SIGNAL, TO-18, TH", Manufacturer="TE CONNECTIVITY"
U3: library part CMP-0073533-3, "350 kHz, Low-Noise, RRIO, CMOS Operational Amplifier for Cost-Sensitive Systems, DGK0008A (VSSOP-8)", Alternate Manufacturer="Texas Instruments", Alternate PartNumber=TLV2333IDGKT
U4: library part CMP-0066526-2, "16-bit Mixed Signal Microcontroller, RHB0032M (VQFN-32)", Alternate Manufacturer="Texas Instruments", Alternate PartNumber=MSP430I2041TRHBT
U5: library part CMP-0084264-1, "I2C-Compatible (2-wire) Serial EEPROM, SOT-23-5", Manufacturer=Microchip
U6: library part CMP-0066602-2, "Dual-Channel High-Speed ESD Protection, DRL0005A (SOT-OTHER-5)", Alternate Manufacturer="Texas Instruments"
U7: library part CMP-0081108-1, "5.5-V, 1.5-A, 100-mohm Load Switch with Output Discharge, DCK0006A (SOT-SC70-6)", Alternate Manufacturer="Texas Instruments", Alternate PartNumber=TPS22919DCKT
U8: library part CMP-0085651-1, "+/-6V, Low IQ Ideal Diode with Input Polarity Protection, DCK0006A (SOT-SC70-6)", Alternate Manufacturer="Texas Instruments", Alternate PartNumber=LM66100DCKT
U9: library part CMP-0860667-1, "3-A BOOST CONVERTER WITH 0.5V ULTRA-LOW INPUT VOLTAGE, DRL0006A (SOT-5X3-6)", Alternate Manufacturer="Texas Instruments"

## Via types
v1: diameter 24, hole 12, Top Layer to Bottom Layer, 83 vias
v2: diameter 20, hole 10, Top Layer to Bottom Layer, 9 vias
v3: diameter 40, hole 20, Top Layer to Bottom Layer, 6 vias
v4: diameter 19.68, hole 7.87, Top Layer to Bottom Layer, 5 vias
v5: diameter 24, hole 15, Top Layer to Bottom Layer, 1 vias

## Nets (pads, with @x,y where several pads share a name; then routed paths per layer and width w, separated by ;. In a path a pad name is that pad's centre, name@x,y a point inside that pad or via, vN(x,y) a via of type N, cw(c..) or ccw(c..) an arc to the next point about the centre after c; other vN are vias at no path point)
3V3: C18.1 C24.2 D4.1 Q1.2 R1.2 R17.2 R20.2 R24.2 R25.2 R30.1 R48.1 R57.2 U5.4 U7.1 | length 2727.9
  Top Layer w15: R48.1@359.75,753.01 359.75,820.29 375.39,835.94 R1.2@405.7,835.94 ; C24.2@805.75,1101.39 808.24,1098.91 v1(808.24,1083.36) ; v1@894.49,904.49 v1(894.49,908.89) ; v1@894.87,904.11 898.84,900.14 988.85,900.14 R17.2@1005.54,916.84 ; v5(904.43,705.87) 904.43,610.45 988.37,526.5 v3(988.37,454.82)
  Top Layer w20: Q1.2@133.82,714.99 181.03,714.99 v3(202.45,693.57) ; v3(319.37,687.31) 359.75,727.69 R48.1@359.75,753.01 ; v1@894.49,904.49 v1@894.87,904.11 ; v3@987.41,455.78 v3(988.37,454.82)
  Top Layer w25: C18.1@519.97,96.39 531.37,96.39 v1(557.37,70.39)
  Bottom Layer w10: 570.69,136.3 572.13,137.73 572.13,161.68
  Bottom Layer w15: 364.37,387.18 364.37,353.76 424.52,293.61 ; v1(894.49,908.89) 894.49,715.8 v5(904.43,705.87)
  Bottom Layer w20: v3(202.45,693.57) 313.11,693.57 v3(319.37,687.31) 319.83,687.31 441.05,566.09 441.05,518.52 D4.1@393.8,471.27 364.37,441.84 364.37,387.18 ; 424.52,293.61 488.73,229.41 488.73,160.08 525.91,122.89 ; R30.1@541.6,71.83 541.6,107.2 ; 570.69,136.3 557.29,122.89 ; 572.13,137.73 584.1,149.71 R24.2@670.75,149.71 672.02,148.44 672.02,128.23 685.85,114.39 833.33,114.39 ; 525.91,122.89 541.6,107.2 ; 525.91,122.89 557.29,122.89 ; 541.6,107.2 557.29,122.89
  Bottom Layer w25: U5.4@572.13,196.99 572.13,161.68 584.1,149.71 ; 833.33,114.39 887.99,169.06 R25.2@887.99,320.39 928.37,320.39 988.37,380.39 v3(988.37,454.82)
  other v1: 761.34,1060.1 761.34,1102.74
AVSS: C2.2 C3.2 C6.2 C7.2 C8.2 C9.2 C11.2 C12.2 C13.2 C14.2 C15.2 C16.2 C17.2 C18.2 C19.2 C20.2 C21.2 C22.2 C23.2 C24.1 C25.2 C26.2 J1.2 J2.4 LS1.2 R10.1 R11.1 R12.1 R13.1 R16.1 R22.1 R23.1 R29.1 R36.1 R52.1 R53.1 R54.1 R59.1 S2.1 S2.3 S3.1 S3.3 U1.4 U3.4 U4.3 U4.4 U4.6 U4.8 U4.10 U4.12 U4.33@661.84,382.9 U5.2 U5.5 U6.4 U7.2 U8.2 U8.3 U8.4 U8.5 U9.4 | length 1333.1
  Top Layer w8: C3.2@424.87,54.39 C3.2@427.37,51.9 ; v4(661.84,414.4) 671.69,424.24
  Top Layer w9.8: 508.38,422.89 508.38,424.46 508.38,432.39 508.65,432.12 516.04,432.12 U4.10@567.35,432.12 ; 531.36,392.75 U4.12@567.35,392.75 598.52,392.75 ; 592.94,454.82 U4.8@592.94,477.39 592.94,490.82 ; 632.32,428.85 U4.6@632.32,477.39 ; 671.69,424.24 U4.4@671.69,477.39
  Top Layer w10: v1@453.72,471.66 473.99,451.39 C19.2@508.38,451.39 ; 508.38,422.89 508.38,413.39 R16.1@507.38,412.39 ; 508.38,432.39 508.38,439.78 ; 531.36,392.75 516.04,392.75 507.38,401.41 R16.1@507.38,412.39 ; 592.94,454.82 618.91,428.85 ; 592.94,490.82 587.37,496.39 519.37,496.39 508.38,485.4 C19.2@508.38,451.39 ; 598.52,392.75 608.36,382.9 v4(630.35,382.9) ; 632.32,428.85 618.91,428.85 ; v4(661.84,382.9) 661.84,385.92 618.91,428.85 ; R16.1@507.38,412.39 507.38,423.46 508.38,424.46 516.04,432.12 508.38,439.78 ; 508.38,439.78 C19.2@508.38,451.39
  Top Layer w12: U7.2@809.08,1029.39 841.37,1029.39 854.61,1016.15 ; v1(854.61,955.46) 854.61,1016.15 ; R23.1@854.99,955.39 R23.1@854.99,955.46 ; C24.1@861.99,1101.39 854.61,1094.01 854.61,1016.15
  Top Layer w15: U3.4@689.47,830.78 689.47,873.12 691.21,874.87 v1(691.21,876.53)
  Top Layer w16: U8.3@163.08,118.8 197.98,118.8
  Top Layer w22: R59.1@401.25,651.27 401.25,679.45 427.57,705.77 C15.2@460.06,705.77 ; C23.2@438.99,505.34 438.99,486.39 v1@453.72,471.66
  Bottom Layer w12: v1(854.61,955.46) 891.43,955.46 920.37,984.39 954.75,984.39 R13.1@956.75,986.39 ; R12.1@956.75,846.39 956.75,801.39 R11.1@957.75,800.39
  Bottom Layer w15: v1(600.99,600.39) 621.91,600.39
  other v1: 287.37,29.77 350.76,30.61 244.94,33.61 513.34,33.61 147.8,40.16 428.37,51.9 415.37,177.89 360.26,242.4 557.37,267.39 937.37,276.39 390.47,290.02 461.37,371.31 413.37,373.27 83.34,397.55 83.34,451.93 453.37,471.31 149.75,480.77 282.75,484.36 83.34,506.31 344.37,578.77 458.75,704.39 496.61,704.69 957.75,795.39 957.76,843.09 690.76,917.47 283.36,927.87 318.14,928.89 83.34,967.62 83.34,1021.99 419.76,1025.74 83.34,1076.37 420.14,1081.23 51.49,1130.97 200.35,1177.78 270.37,1179.95 347.09,1179.95 470.11,1179.95 524.49,1179.95 578.87,1179.95
  other v3: 156.37,572.39 287.37,572.39 212.88,1071.22
  other v4: 661.84,351.41 693.34,382.9
BATT_PLUS: C2.1 C6.1 D4.2 L1.2 R18.2 R27.2 U9.3 | length 399.6
  Top Layer w18: R18.2@202.75,216.39 v1(202.75,247.77)
  Bottom Layer w20: L1.2@253.37,306.74 240.37,319.74 240.37,495.02 263.87,518.52 366.24,518.52 D4.2@393.8,546.08
  other v1: 160.75,266.77
BOOST_EN: C26.1 D3.1 R52.2 U9.2 | length 244.3
  Top Layer w15: D3.1@252.75,289.05 260.09,281.72 R52.2@309.37,281.72 309.37,201.96 C26.1@327.37,183.96 310.64,167.22 v2(287.03,167.22)
  Bottom Layer w11.8: v2(287.03,167.22) 294.2,174.39 U9.2@316.24,174.39
BOOST_EN_SIG: D3.2 R26.1 R53.2 U4.32 | length 1591.1
  Top Layer w10: U4.32@756.33,451.8 756.33,490.72 828.38,562.77 v1(828.38,570.86)
  Top Layer w15: v1(208.75,371.06) 214.05,371.06 D3.2@252.75,332.36
  Bottom Layer w15: R53.2@83.75,778.64 R53.2@86.91,778.64 R26.1@86.91,835.53 ; v1(208.75,371.06) 196.75,383.06 196.75,602.06 156.37,642.44 156.37,710.85 114.83,752.39 110.29,756.93 ; v1(828.38,570.86) 789.87,532.36 529.16,532.36 335.65,725.87 253.37,725.87 200.61,778.64 110.29,778.64 ; 110.29,756.93 99.02,768.2 99.02,778.64 110.29,778.64 ; 110.29,756.93 110.29,778.64
COM0: J4.9 R4.1 R10.2 R33.2 | length 526.9
  Bottom Layer w10: R33.2@854.36,363.02 873.32,363.02 948.33,438.02 948.33,463.02 983.39,498.08 999.15,498.08 1034.8,533.73 1034.8,630.59 1013.99,651.39 R10.2@1005.99,651.39 1005.99,698.39 R4.1@1004.99,699.39 1066.29,699.39 J4.9@1078.37,687.31
COM1: J4.10 R5.1 R11.2 R44.2 | length 611
  Top Layer w10: v1(1000.37,619.39) 1039.37,658.39 1039.37,727.05 J4.10@1078.37,766.05
  Bottom Layer w10: R44.2@854.36,399.39 876.67,399.39 927.39,450.11 927.39,468.19 1000.37,541.17 v1(1000.37,619.39) ; v1@995.37,624.39 v1@1000.37,624.39
  Bottom Layer w12: R5.1@1004.99,747.39 R11.2@1004.99,795.39 1049.03,795.39 J4.10@1078.37,766.05
COM2: J4.11 R6.1 R12.2 R45.2 | length 664.5
  Top Layer w10: v1(976.37,592.64) 976.37,641.62 1019.75,685 1019.75,791.87 1058.27,830.39 1078.37,830.39 1063.96,844.79 J4.11@1078.37,844.79
  Bottom Layer w10: R45.2@854.36,435.39 867.79,435.39 976.37,543.98 v1(976.37,592.64)
  Bottom Layer w12: R6.1@1003.99,890.74 1003.99,843.39 1076.97,843.39 J4.11@1078.37,844.79
COM3: J4.12 R7.1 R13.2 R46.2 | length 678
  Top Layer w10: v1@951.37,624.39 951.37,648.88 1000.37,697.88 1000.37,845.53 J4.12@1078.37,923.53
  Bottom Layer w10: R46.2@854.36,472.39 872.35,472.39 951.37,551.42 v1(951.37,619.39)
  Bottom Layer w12: R13.2@1003.99,986.39 R7.1@1003.99,938.39 1063.51,938.39 J4.12@1078.37,923.53
I2C_SCL: R25.1 R38.2 R42.2 TP1.1 U5.1 | length 422.4
  Bottom Layer w10: TP1.1@600.37,332.39 617.86,332.39 618.86,331.39 636.86,331.39 666.61,301.64 ; R42.2@727.37,293.4 731.37,289.4 R38.2@731.37,254.39 716.38,254.39 698.97,271.79 U5.1@666.61,271.79 666.61,301.64 ; R25.1@840.75,320.39 811.32,320.39 788.32,343.39 708.37,343.39 666.61,301.64
I2C_SDA: R24.1 R41.2 R50.2 TP2.1 U5.3 | length 301.4
  Bottom Layer w8: U5.3@666.61,196.99 U5.3@672.02,202.39
  Bottom Layer w12: R41.2@789.35,229.4 790.37,228.39 R50.2@790.37,192.39
  Bottom Layer w15: U5.3@666.61,196.99 671.21,192.39 705.8,192.39 ; TP2.1@767.69,154.71 762.69,149.71 R24.1@717.99,149.71 717.99,180.2 ; R50.2@790.37,192.39 730.19,192.39 ; 705.8,192.39 713.91,192.39 ; 705.8,192.39 717.99,180.2 ; 713.91,192.39 730.19,192.39 ; 713.91,192.39 717.99,188.32 717.99,180.2 ; 717.99,180.2 730.19,192.39
MCU_VCC: D4.3 J2.1 R15.2 R31.1 R56.2 | length 1071
  Top Layer w15: v1(427.04,328.96) 427.04,303.61 R15.2@441.05,289.61 ; v1(536.03,169.86) 536.03,164.32 642.97,57.39 J2.1@653.26,57.39
  Bottom Layer w15: v1(427.04,328.96) 450.36,328.96 ; v1(536.03,169.86) 521.54,184.35 521.54,257.77 470.37,308.94 ; R56.2@867.79,518.77 843.84,518.77 825.9,500.82 529.16,500.82 521.31,508.67 D4.3@488.29,508.67 488.29,481.09 506.99,462.39 R31.1@506.99,417.39 503.61,414.01 503.61,371.31 470.37,338.07 ; 450.36,328.96 451.04,328.96 456.15,323.85 470.37,338.07 ; 450.36,328.96 470.37,308.94 ; 470.37,308.94 470.37,338.07
NetC3_1: C3.1 C5.2 C25.1 R30.2 R35.2 U9.6
  other v1: 357.13,108.39 427.75,115.27 373.13,127.39
NetC4_1: C4.1 R3.1 R8.2 U3.2 | length 240.9
  Top Layer w10: U3.2@689.47,779.6 724.57,779.6 746.99,802.01 C4.1@767.37,802.01
  Bottom Layer w15: R8.2@715.99,701.39 715.99,784.01 734.37,802.39 v1(767.37,802.39) 768.87,802.39 R3.1@776.37,809.89
NetC4_2: C4.2 R3.2 R9.1 U3.1 | length 78.2
  Top Layer w10: U3.1@689.47,754.01 766.61,754.01 C4.2@767.37,754.77
  other v1: 767.37,755.01
NetC5_1: C5.1 R35.1 R36.2 U9.1 | length 56.9
  Top Layer w16: v1(303.37,114.39) 303.37,61.76 302.87,61.27 R36.2@305.37,58.77
NetC8_1: C8.1 C12.1 R31.2 U4.13 | length 179.4
  Top Layer w8: C12.1@407.37,420.02 C12.1@408.37,419.02 ; C8.1@461.43,419.02 507.38,373.06 U4.13@567.35,373.06
  Top Layer w12: C12.1@408.37,419.02 C8.1@461.37,419.02 C8.1@461.43,419.02
  other v1: 459.99,417.31 413.49,418.68
NetC13_1: C13.1 U4.14 | length 36
  Top Layer w8: C13.1@531.36,353.39 U4.14@567.35,353.38
NetC14_1: C14.1 R1.1 R19.2 U3.5 | length 285.3
  Top Layer w15: R1.1@405.7,906.8 410.18,911.28 v1(457.99,911.28) 457.99,846.63 473.84,830.78 U3.5@514.27,830.78
  Bottom Layer w15: R19.2@444.61,813.64 444.04,814.21 C14.1@444.04,866 444.04,897.33 v1(457.99,911.28)
NetC15_1: C15.1 R48.2 U3.8 | length 107.7
  Top Layer w10: C15.1@460.06,753.01 C15.1@461.05,754.01
  Top Layer w12: R48.2@406.99,753.01 C15.1@460.06,753.01 ; C15.1@461.05,754.01 U3.8@514.27,754.01
NetC17_1: C17.1 D2.1 R23.2 U7.3 | length 206.5
  Top Layer w12: U7.3@809.08,1003.8 808.24,1002.96 v1(808.24,955.42) 808.24,931.98 870.37,869.85 D2.1@870.37,823.39
NetC19_1: C19.1 U4.9 | length 33.2
  Top Layer w9.8: C19.1@534.36,451.39 534.77,451.8 U4.9@567.35,451.8
NetC21_1: C21.1 R27.1 R29.2 R49.1 S2.2 S2.4 | length 200.2
  Top Layer w16: R27.1@97.37,314.02 149.37,366.02 v1(149.37,433.77)
  Bottom Layer w16: v1(149.37,433.77) 149.75,433.39 R29.2@149.75,375.03
  other v1: 282.37,387.18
